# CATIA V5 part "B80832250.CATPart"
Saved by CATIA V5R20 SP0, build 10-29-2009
Part number: B80832250
Revision: 3
Definition: design
Nomenclature: B80832250
Source: made
Description: NOT SPECIFIED
Bounding box of the stored display mesh (mm): x -18.312 to 18.312, y -18.5 to 18.5, z 0 to 250
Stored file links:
  C:\Users\Raffaele\Desktop\3D X SITO CF\BOLEX\4-PILLAR REF 808\B80832250.CATPart
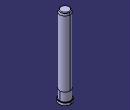
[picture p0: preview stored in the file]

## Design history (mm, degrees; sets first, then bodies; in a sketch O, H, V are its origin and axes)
Body1 "MANIFOLD_SOLID_BREP #450" (main body)
  Solid1: solid without history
